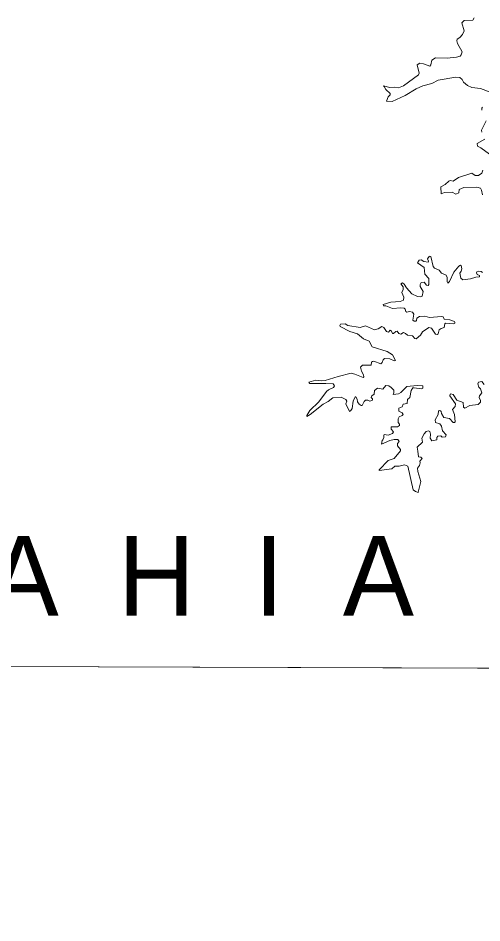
# Model space of a CAD drawing. Extents: x -1643653 to 4543381, y 1624270 to 13878484.
# Drawn here: x 578066 to 580395, y 8908709 to 8913255 of the extents above; entities that cross this region are included whole.
import ezdxf

# ---------------------------------------------------------------- set-up
doc = ezdxf.new("R2010")
doc.units = 0
doc.header["$LTSCALE"] = 200
doc.layers.add('1', color=7, linetype='Continuous', lineweight=13)
doc.layers.add('6', color=7, linetype='Continuous', lineweight=13)

msp = doc.modelspace()

# ---------------------------------------------------------------- linework, layer by layer
at = {"layer": '1', "lineweight": 25}
msp.add_spline([(814781, 9009175.5), (814787.2, 9009173.4), (814796.9, 9009173.4), (814799.4, 9009172.4), (814805.1, 9009174.5), (814805.6, 9009176.5), (814811.7, 9009179.5), (814811.7, 9009179.5), (814801.5, 9009181), (814790.7, 9009181.5), (814784.1, 9009183.1), (814777.4, 9009185.1), (814778.4, 9009175.5)], degree=3, dxfattribs=at)
at = {"layer": '6'}
msp.add_line((574653.9, 8910009.3), (626625.7, 8909822.1), dxfattribs=at)
msp.add_lwpolyline([(585645.8, 8921027.3), (574684.9, 8921064.7), (574653.9, 8910009.3), (585614.8, 8909969.8)], close=True, dxfattribs=at)
for points in [[(580357.1, 8913255.3), (580350.3, 8913243.9), (580306.6, 8913242.2), (580295.1, 8913231.1), (580306.9, 8913190.7), (580297.5, 8913171.9), (580284.9, 8913157.6), (580271.7, 8913148.7), (580268.7, 8913141), (580272.1, 8913127), (580295.9, 8913084.6), (580291.7, 8913070.9), (580285.7, 8913063.8), (580267, 8913057.8), (580220.3, 8913053.9), (580161.6, 8913055.2), (580143.4, 8913043.7), (580138.7, 8913020), (580133.1, 8913012.8), (580102.1, 8913025.1), (580083.4, 8913027.6), (580083.4, 8913027.6), (580070.8, 8913020.3), (580080.9, 8912977.5), (580076.7, 8912970.2), (580002.3, 8912914.6), (579976.4, 8912903.6), (579958.6, 8912907.8), (579932.2, 8912906.9), (579901.5, 8912914.6), (579903.9, 8912911)], [(579903.9, 8912911), (579913.6, 8912896.3), (579934.3, 8912875.4), (579934.3, 8912868.7), (579924.2, 8912858.5), (579916.2, 8912837.4), (579944.1, 8912836.4), (580010.4, 8912865.3), (580065.6, 8912899.7), (580098.8, 8912915), (580143, 8912926.9), (580176.2, 8912942.2), (580264.5, 8912958.8)], [(580264.5, 8912958.8), (580284, 8912956.2), (580296.7, 8912946.9), (580302.3, 8912933.7), (580322.3, 8912915.4), (580344.3, 8912906.9), (580388.5, 8912901.4), (580436.2, 8912882.3)], [(580397.9, 8912807.9), (580394.1, 8912802.5), (580395.3, 8912793)], [(580416.6, 8912737.9), (580392.8, 8912690.9), (580395.3, 8912681.4)], [(580409.4, 8912645.7), (580371.5, 8912623.9), (580372.4, 8912610.8), (580389.8, 8912603.1), (580432.7, 8912571.7)], [(580400.4, 8912490.6), (580394.5, 8912476.2), (580378.8, 8912463.8), (580361.3, 8912463.8), (580344, 8912475.3), (580277.2, 8912453.6), (580250.1, 8912436.2), (580235.2, 8912438.7), (580228.4, 8912436.2), (580210.1, 8912419.2), (580188.4, 8912406.4), (580190.3, 8912372.1), (580206.7, 8912378.9), (580246.6, 8912380.5), (580264.5, 8912369.9), (580278.5, 8912376.7), (580280.7, 8912393.7), (580303.6, 8912403.1), (580368.9, 8912405.2), (580388.3, 8912400.7), (580393.2, 8912391), (580397.9, 8912367.4)], [(580121.8, 8912045), (580126.4, 8912034.3), (580125.1, 8912028.8), (580103.5, 8912031.8), (580090.2, 8912041.1), (580080.1, 8912039), (580072, 8912024.5), (580106, 8912001.6), (580109.4, 8911967.6), (580128.1, 8911946.4), (580128.1, 8911916.3), (580125.1, 8911911.6), (580117.5, 8911913.2), (580104.7, 8911927.6), (580090.3, 8911925.9), (580085.2, 8911916.6), (580085.6, 8911905.5), (580099.6, 8911880.5), (580095.3, 8911858), (580087.8, 8911854.2), (580071.2, 8911856.7), (580043.6, 8911869), (580016.8, 8911899.2), (580005.3, 8911918.7), (579996, 8911925.5), (579988.8, 8911920.5), (580000.2, 8911904.2), (580000.3, 8911891.6), (579993.9, 8911876.3), (580003.6, 8911852.9), (580001.9, 8911838), (579984.9, 8911831.7), (579938.1, 8911827.4), (579900, 8911815.9), (579900.8, 8911810), (579912.2, 8911809.9), (579946.7, 8911796.4), (579987.5, 8911799.3), (580004.4, 8911796.8), (580009.5, 8911793), (580013.4, 8911780.7), (580018, 8911777.7), (580031.7, 8911780.7), (580046.5, 8911778.1), (580052.9, 8911767), (580048.6, 8911737.4), (580055.3, 8911731.8), (580063, 8911731.4), (580067.3, 8911734.8), (580068.2, 8911746.7), (580081, 8911756.4), (580109, 8911757.7), (580132.6, 8911751.3), (580193.1, 8911755.6), (580201.1, 8911753.5), (580205.8, 8911742.5), (580233.9, 8911739.4), (580256.8, 8911730.5), (580259.8, 8911726.7), (580258.5, 8911722.5), (580252.5, 8911719.5), (580213, 8911722), (580208.4, 8911718.2), (580206.2, 8911700), (580190.1, 8911694.8), (580181.2, 8911688.5), (580175.7, 8911669.3), (580170.6, 8911665.5), (580162.9, 8911666.4), (580142.1, 8911697.4), (580128.5, 8911700.8), (580097.5, 8911679.1), (580087.3, 8911662.6), (580065.8, 8911643), (580057.6, 8911644.7), (580045.9, 8911659.3), (580021.8, 8911661.3), (580011.7, 8911671), (580001.1, 8911675.7), (579987.5, 8911666.8), (579977.7, 8911670.3), (579969.8, 8911681.2), (579969.8, 8911681.2), (579962.8, 8911680.4), (579951.3, 8911670.2), (579946, 8911670.6), (579942, 8911682.1), (579933.9, 8911686.7), (579925.8, 8911677.4), (579916.1, 8911680), (579902.5, 8911700.3), (579893.2, 8911705.4), (579874.8, 8911693.1), (579856.7, 8911689.3), (579809.9, 8911708.8), (579784.4, 8911700.4), (579722.5, 8911710.5), (579709.1, 8911719.2), (579684.5, 8911717.3), (579681.6, 8911710.5), (579681.8, 8911710)], [(580398.7, 8911976.5), (580392.2, 8911981.7), (580378, 8911983.3), (580370.2, 8911979.9), (580368.1, 8911974.8), (580371.9, 8911966.8), (580383.4, 8911960.8), (580382.6, 8911954.1), (580364.8, 8911954), (580338.3, 8911944.2), (580298.8, 8911940.4), (580289.5, 8911947.6), (580283.6, 8911973.1), (580283.6, 8911973.1), (580290.8, 8911983.4), (580293.8, 8911995.2), (580291.7, 8912011.3), (580286.9, 8912013), (580279.8, 8912008.8), (580253.5, 8911979.1), (580232.2, 8911931.5), (580223.7, 8911922.6), (580220.3, 8911930.6), (580221, 8911952.3), (580216.2, 8911962.5), (580193.1, 8911973.6), (580181.1, 8911988), (580157.4, 8911999.1), (580150.6, 8912007.1), (580138.3, 8912056.4), (580134.5, 8912058.9), (580129.8, 8912057.2), (580121.8, 8912045)], [(579681.8, 8911710), (579684.2, 8911705), (579731.7, 8911679.6), (579769.9, 8911668.1), (579800.4, 8911643.1), (579829, 8911631.1), (579843.9, 8911602.6), (579919.9, 8911580.6), (579946.2, 8911563.1), (579961.1, 8911533.8), (579955.1, 8911532.6), (579933.5, 8911542.8), (579906.8, 8911544), (579899.6, 8911537.3), (579894.4, 8911523.7), (579888, 8911518.6), (579852.9, 8911530.4), (579845.7, 8911530), (579840.1, 8911525.8), (579839.2, 8911510.4), (579795.4, 8911511.7), (579785.7, 8911501.2), (579789.9, 8911480.3), (579800.5, 8911462.4), (579802.2, 8911453), (579798.4, 8911449.3), (579757.4, 8911466.6), (579738.5, 8911470.5), (579673.2, 8911454.8), (579607.7, 8911433.6), (579588.9, 8911432.7), (579560.9, 8911436.5), (579525.9, 8911424.9), (579528, 8911422.6)], [(579528, 8911422.6), (579531.2, 8911419.1), (579611.9, 8911419.5), (579648.1, 8911417), (579654.8, 8911407.6), (579649.2, 8911399.1), (579625.5, 8911387.7), (579614.5, 8911378.8), (579575.8, 8911326.1), (579531.2, 8911283.6), (579515.4, 8911258), (579515.7, 8911254.2)], [(579515.7, 8911254.2), (579515.9, 8911252.7), (579533.7, 8911262.8), (579597.4, 8911315.8), (579622.9, 8911328.2), (579646.7, 8911346.9), (579689.2, 8911351.1), (579712.6, 8911338.4), (579716.8, 8911330.3), (579712.2, 8911317.1), (579730.1, 8911279), (579736.4, 8911282.8), (579743.6, 8911293.4), (579748.3, 8911330.7), (579758.5, 8911352.4), (579761.8, 8911352), (579768.2, 8911341), (579769.9, 8911327.4), (579779.3, 8911315.1), (579788.2, 8911309.1), (579794.6, 8911309.1), (579803.6, 8911328.8), (579810.7, 8911334.5), (579822.2, 8911334.6), (579833.2, 8911329.5), (579846.4, 8911334.6), (579846.4, 8911341.8), (579838.4, 8911348.8), (579842.2, 8911357.5), (579853.6, 8911366), (579855.8, 8911383), (579870.2, 8911395.3), (579896.9, 8911390.7), (579912.3, 8911409.3), (579927.1, 8911407.2), (579939.5, 8911399.5), (579952.6, 8911385.1), (579953, 8911372.4), (579948.8, 8911363.1), (579976.4, 8911367.7), (579987.9, 8911374.1), (580018.5, 8911404.6), (580018.5, 8911404.6), (580070.7, 8911408.9), (580097.9, 8911407.7), (580098.3, 8911395), (580092, 8911392.4), (580055.8, 8911397.9), (580048.6, 8911396.5), (580040.1, 8911383.4), (580033.3, 8911349.3), (580020.9, 8911339.4), (580019.3, 8911318.9), (579999, 8911315), (579995.1, 8911302.3), (579977.7, 8911295), (579978.1, 8911280.6), (579995.1, 8911271.3), (580000.6, 8911264.1), (579994.3, 8911257.7), (579979, 8911251.3), (579974.3, 8911240.7), (579973.9, 8911222.4), (579980.7, 8911215.2), (579981.5, 8911207.5), (579972.2, 8911202), (579939.9, 8911201.6), (579939.9, 8911189.3), (579951.8, 8911177), (579946.3, 8911167.7), (579923.9, 8911160), (579905.1, 8911163.3), (579902.1, 8911159.9), (579902.1, 8911147.2), (579897.9, 8911135.4), (579894, 8911132.7), (579891, 8911113.7), (579932.4, 8911132.8), (579955.2, 8911137.9), (579973.8, 8911137.4), (579980.2, 8911127.7), (579971.3, 8911117.8), (579971.3, 8911106.5), (579985.7, 8911087.3), (579985.8, 8911081.4), (579955.2, 8911042.7), (579923.7, 8911031.6), (579879.1, 8910985.1), (579879.4, 8910984)], [(580075.2, 8910873.2), (580087.7, 8910926.3), (580073.3, 8910977.3), (580072.4, 8910994.2), (580082.6, 8911007.1), (580086, 8911020.6), (580083.5, 8911029.6), (580094.5, 8911042.7), (580087.7, 8911048.6), (580076.3, 8911049.9), (580074.1, 8911078.3), (580069.9, 8911098.8), (580096.2, 8911124.2), (580093.3, 8911144.8), (580104.7, 8911166.7), (580115.8, 8911178.6), (580126.2, 8911181.2), (580133.6, 8911177.4), (580137.8, 8911164.2), (580135.3, 8911143.8), (580144.2, 8911130.7), (580168.8, 8911136.6), (580168.5, 8911147.3), (580173.6, 8911154.8), (580188.4, 8911156.1), (580196.2, 8911149.3), (580212.2, 8911151.1), (580215.1, 8911160.8), (580197, 8911181.2), (580191.8, 8911205.4), (580184.5, 8911216.1), (580161.7, 8911223.3), (580160.4, 8911237.3), (580176.1, 8911263.6), (580177.8, 8911281.5), (580183.4, 8911283.1), (580190.9, 8911278.9), (580192.3, 8911267.7), (580204.2, 8911248.3), (580233.2, 8911242.7), (580251.3, 8911223.7), (580257.2, 8911223.7), (580260.2, 8911227.1), (580257.7, 8911262.8), (580248.3, 8911288), (580261.1, 8911302.7), (580261.9, 8911317.5), (580261.9, 8911317.5), (580233.5, 8911356.3), (580235.2, 8911364.7), (580239.9, 8911366.4), (580250.8, 8911363.5), (580269.2, 8911335), (580301.4, 8911323.1), (580302.7, 8911299.3), (580309, 8911295.1), (580335, 8911309.1), (580375.7, 8911312.9), (580387.7, 8911324.8), (580388.9, 8911334.1), (580381.8, 8911348.6), (580382.6, 8911357), (580394, 8911371.6), (580387.6, 8911391.9), (580379.2, 8911400.4), (580374.1, 8911417.8), (580377.9, 8911425.9), (580394, 8911428.9), (580406.8, 8911413.6)], [(579879.4, 8910984), (579879.8, 8910982.2), (579942.4, 8910990.9), (579958.6, 8911004), (579979, 8911003.2), (580005.8, 8911009.6), (580022.6, 8911004.5), (580049.7, 8910884.3), (580061, 8910876.2), (580074.9, 8910871.9), (580075.2, 8910873.2)]]:
    msp.add_lwpolyline(points, dxfattribs=at)

# ---------------------------------------------------------------- texts
msp.add_text('B  A  H  I  A', height=400, dxfattribs=at).set_placement((577259.8, 8910252.7))

doc.saveas('drawing.dxf')
